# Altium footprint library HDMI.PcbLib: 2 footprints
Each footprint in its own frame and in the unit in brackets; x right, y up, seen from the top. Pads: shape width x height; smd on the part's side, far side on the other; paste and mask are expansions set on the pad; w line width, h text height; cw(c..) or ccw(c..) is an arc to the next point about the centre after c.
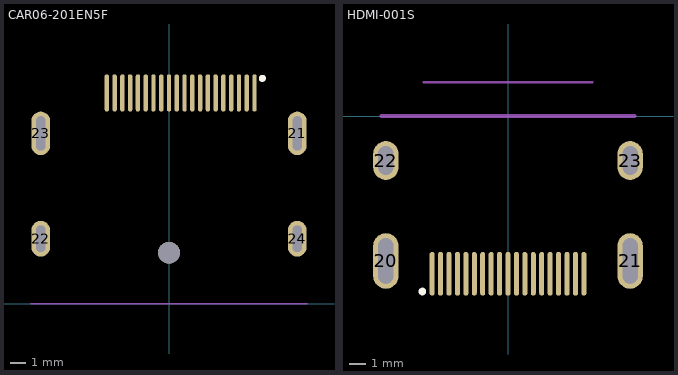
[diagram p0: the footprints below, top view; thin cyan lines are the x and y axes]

## CAR06-201EN5F [mm]
pads (24):
  oval 0.28x2.4 smd: 1(5.5,13.56) 2(5,13.56) 3(4.5,13.56) 4(4,13.56) 5(3.5,13.56) 6(3,13.56) 7(2.5,13.56) 8(2,13.56) 9(1.5,13.56) 10(1,13.56) 11(0.5,13.56) 12(0,13.56) 13(-0.5,13.56) 14(-1,13.56) 15(-1.5,13.56) 16(-2,13.56) 17(-2.5,13.56) 18(-3,13.56) 19(-3.5,13.56) 20(-4,13.56)
  oval 1.2x2.8 hole 0.6 slot 2.2 at 90 deg: 21(8.25,10.96) 23(-8.25,10.96)
  oval 1.2x2.3 hole 0.6 slot 1.7 at 90 deg: 22(-8.25,4.18) 24(8.25,4.18)
via 0,3.28 diameter 1.4 hole 1.4
Top Overlay:
  circle w0.254: c6,14.5 r0.099
Mechanical 1:
  lines w0.1: -8.89,0 8.89,0
3D body "DP-SMD_CAR06-201EN5F.step": height 7.21, standoff -1.95, extent -9.262,-1.032 9.262,14.02

## HDMI-001S [mm]
pads (23):
  oval 0.3x2.6 smd: 1(-4.5,-9.36) 2(-4,-9.36) 3(-3.5,-9.36) 4(-3,-9.36) 5(-2.5,-9.36) 6(-2,-9.36) 7(-1.5,-9.36) 8(-1,-9.36) 9(-0.5,-9.36) 10(0,-9.36) 11(0.5,-9.36) 12(1,-9.36) 13(1.5,-9.36) 14(2,-9.36) 15(2.5,-9.36) 16(3,-9.36) 17(3.5,-9.36) 18(4,-9.36) 19(4.5,-9.36)
  oval 1.5x3.3 hole 0.9 slot 2.7 at 90 deg: 20(-7.25,-8.6) 21(7.25,-8.6)
  oval 1.5x2.3 hole 0.9 slot 1.7 at 90 deg: 22(-7.25,-2.64) 23(7.25,-2.64)
Top Overlay:
  circle w0.254: c-5.08,-10.414 r0.099
Mechanical 1:
  lines w0.254: -7.5,0 7.5,0
Mechanical 15:
  lines w0.127: -5,2 5,2
3D body "HDMI-SMD_HDMI-001S.step": height 6.24, standoff -2.28, extent -7.5,-10.02 7.5,2.13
